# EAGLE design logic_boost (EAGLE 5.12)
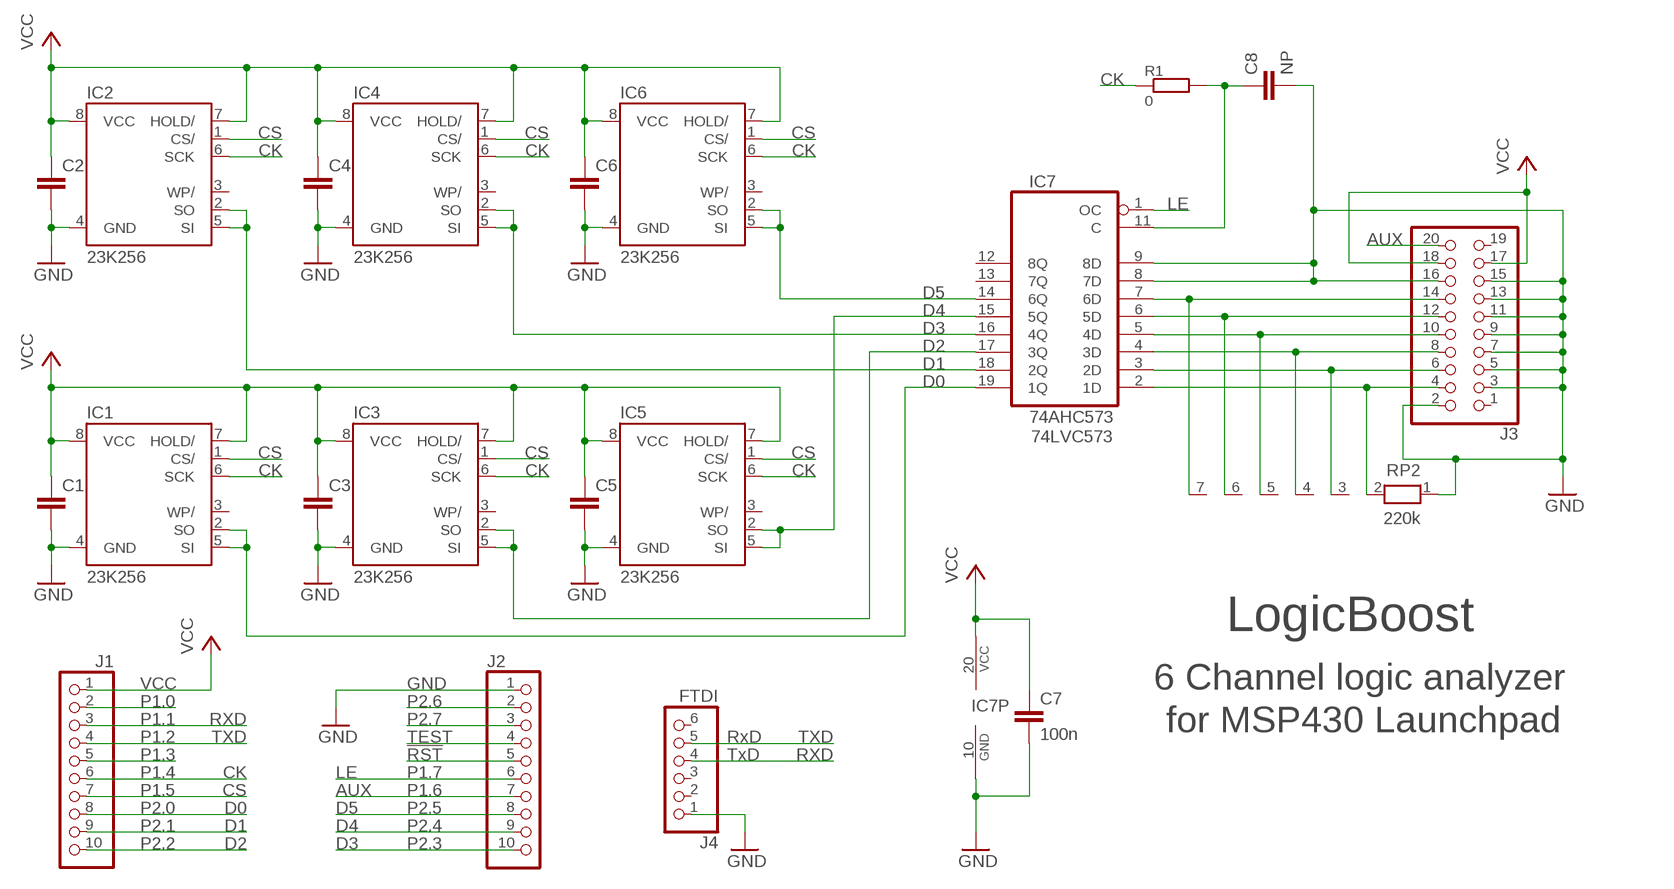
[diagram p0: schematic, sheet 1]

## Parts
C1  C-EU025-025X050  [C025-025X050]
C2  C-EU025-025X050  [C025-025X050]
C3  C-EU025-025X050  [C025-025X050]
C4  C-EU025-025X050  [C025-025X050]
C5  C-EU025-025X050  [C025-025X050]
C6  C-EU025-025X050  [C025-025X050]
C7  100n  C-EU025-025X050  [C025-025X050]
C8  NP  C-EU025-025X050  [C025-025X050]
IC1  23K256  AT25P  [DIL08]
IC2  23K256  AT25P  [DIL08]
IC3  23K256  AT25P  [DIL08]
IC4  23K256  AT25P  [DIL08]
IC5  23K256  AT25P  [DIL08]
IC6  23K256  AT25P  [DIL08]
IC7  74AHC573  74HC573N  [DIL20]
J1  PH1X10OCT076  [PH1X10OCT76]
J2  PH1X10OCT076  [PH1X10OCT76]
J3  PINHD-2X10  [2X10]
J4  FTDI  PH1X6OCT76  [PH1X6OCT76]
R1  0  EW30  [EW30]
RP2  220k  RN06  [RN-7]

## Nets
!RST: J2.5
AUX: J2.7 J3.20
CK: IC1.6(SCK) IC2.6(SCK) IC3.6(SCK) IC4.6(SCK) IC5.6(SCK) IC6.6(SCK) J1.6 R1.1
CS: IC1.1(CS/) IC2.1(CS/) IC3.1(CS/) IC4.1(CS/) IC5.1(CS/) IC6.1(CS/) J1.7
D0: IC1.2(SO) IC1.5(SI) IC7.19(1Q) J1.8
D1: IC2.2(SO) IC2.5(SI) IC7.18(2Q) J1.9
D2: IC3.2(SO) IC3.5(SI) IC7.17(3Q) J1.10
D3: IC4.2(SO) IC4.5(SI) IC7.16(4Q) J2.10
D4: IC5.2(SO) IC5.5(SI) IC7.15(5Q) J2.9
D5: IC6.2(SO) IC6.5(SI) IC7.14(6Q) J2.8
GND: C1.2 C2.2 C3.2 C4.2 C5.2 C6.2 C7.2 C8.2 IC1.4(GND) IC2.4(GND) IC3.4(GND) IC4.4(GND) IC5.4(GND) IC6.4(GND) IC7.8(7D) IC7.9(8D) IC7.10(GND) J2.1 J3.2 J3.3 J3.5 J3.7 J3.9 J3.11 J3.13 J3.15 J3.16 J4.1 RP2.1
LE: IC7.1(OC) J2.6
N$2: C8.1 IC7.11(C) R1.2
N$3: IC7.2(1D) J3.4 RP2.2
N$4: IC7.3(2D) J3.6 RP2.3
N$5: IC7.4(3D) J3.8 RP2.4
N$6: IC7.5(4D) J3.10 RP2.5
N$7: IC7.6(5D) J3.12 RP2.6
N$8: IC7.7(6D) J3.14 RP2.7
P1.0: J1.2
P1.3: J1.5
P2.6: J2.2
P2.7: J2.3
RXD: J1.3 J4.4
TEST: J2.4
TXD: J1.4 J4.5
VCC: C1.1 C2.1 C3.1 C4.1 C5.1 C6.1 C7.1 IC1.7(HOLD/) IC1.8(VCC) IC2.7(HOLD/) IC2.8(VCC) IC3.7(HOLD/) IC3.8(VCC) IC4.7(HOLD/) IC4.8(VCC) IC5.7(HOLD/) IC5.8(VCC) IC6.7(HOLD/) IC6.8(VCC) IC7.20(VCC) J1.1 J3.17 J3.18
Unconnected: IC1.3(WP/) IC2.3(WP/) IC3.3(WP/) IC4.3(WP/) IC5.3(WP/) IC6.3(WP/) IC7.12(8Q) IC7.13(7Q) J3.1 J3.19 J4.2 J4.3 J4.6

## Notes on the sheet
- 74LVC573
- LogicBoost
- 6 Channel logic analyzer
- P1.1
- for MSP430 Launchpad
- P1.2 | RxD
- TxD
- P1.4 | P1.7
- P1.5 | P1.6
- P2.0 | P2.5
- P2.1 | P2.4
- P2.2 | P2.3

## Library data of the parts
C1-C8 = rcl:C-EU: CAPACITOR, European symbol
IC1-IC6 = atmel:AT25*: SPI bus serial EEPROM; MPN: CAT25040LI-G; OC_FARNELL: 1718045; OC_NEWARK: 06R0588
IC7 = 74xx-us:74*573: 8-bit D latch BUS DRIVER
J1 J2 = MY_CONN:PH1X10
J3 = pinhead:PINHD-2X10: PIN HEADER
J4 = MY_CONN:PH1X6
R1 = my_resistor:EW30
RP2 = resistor-net:RN06: RESISTOR NETWORK; OC_FARNELL: unknown; OC_NEWARK: unknown

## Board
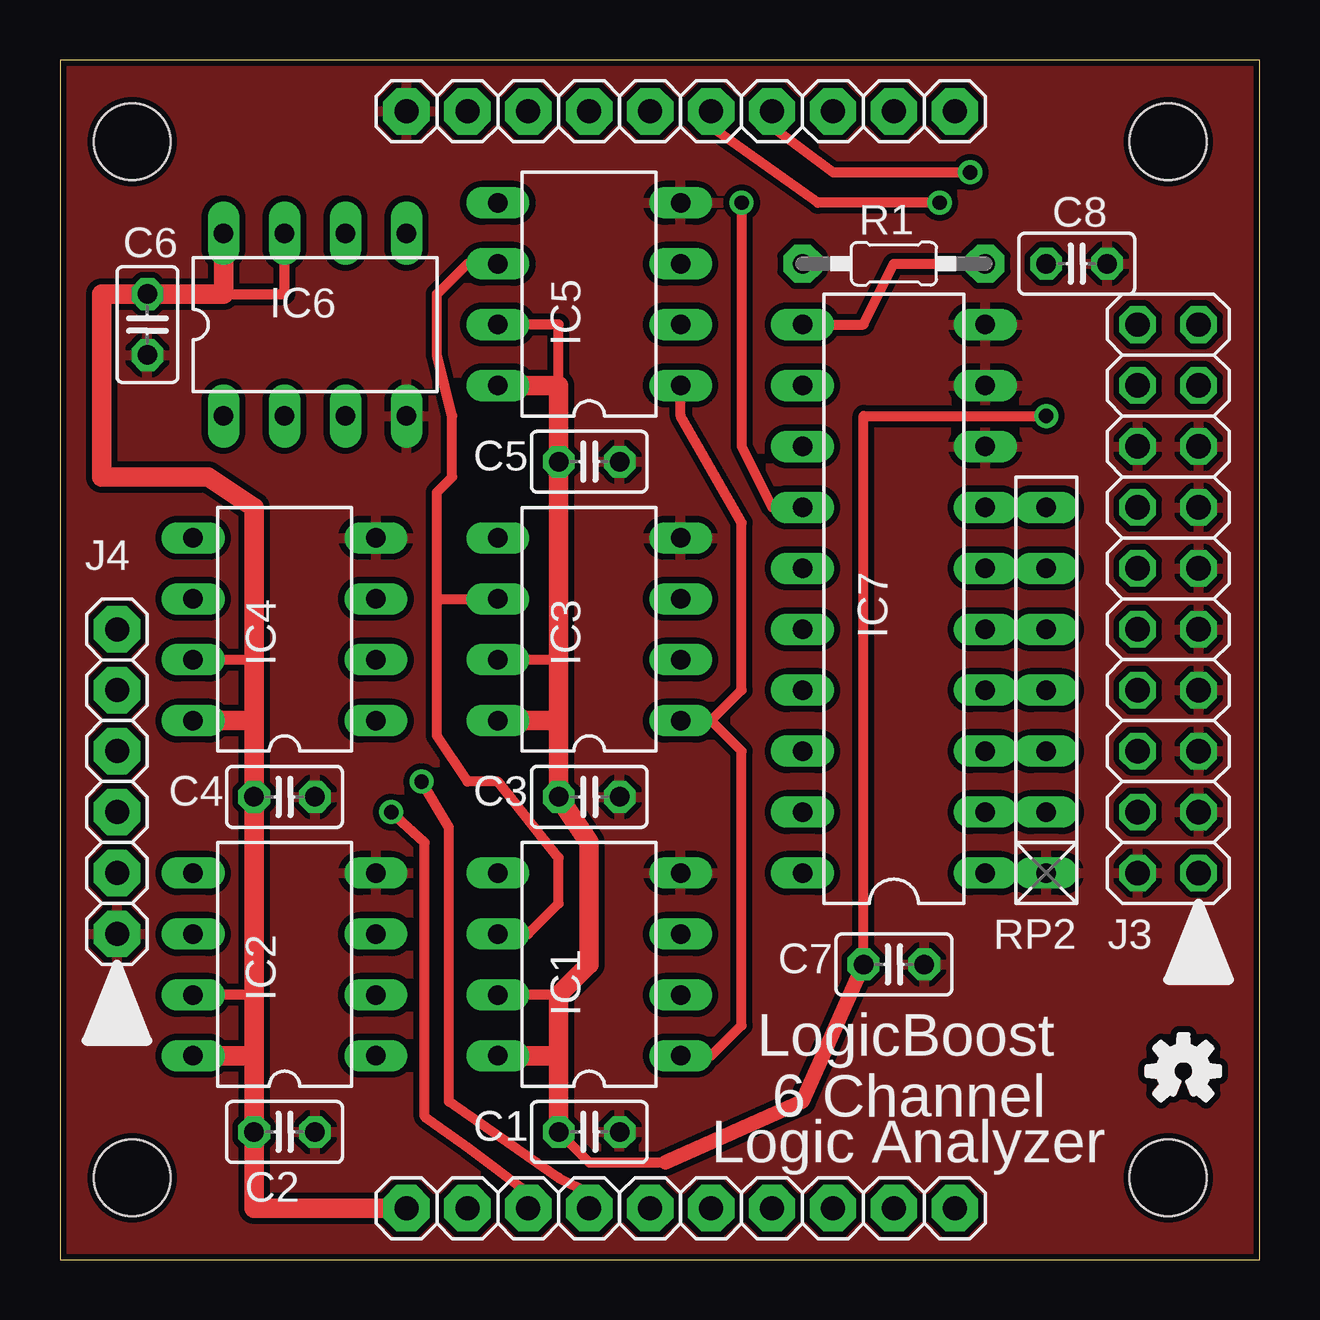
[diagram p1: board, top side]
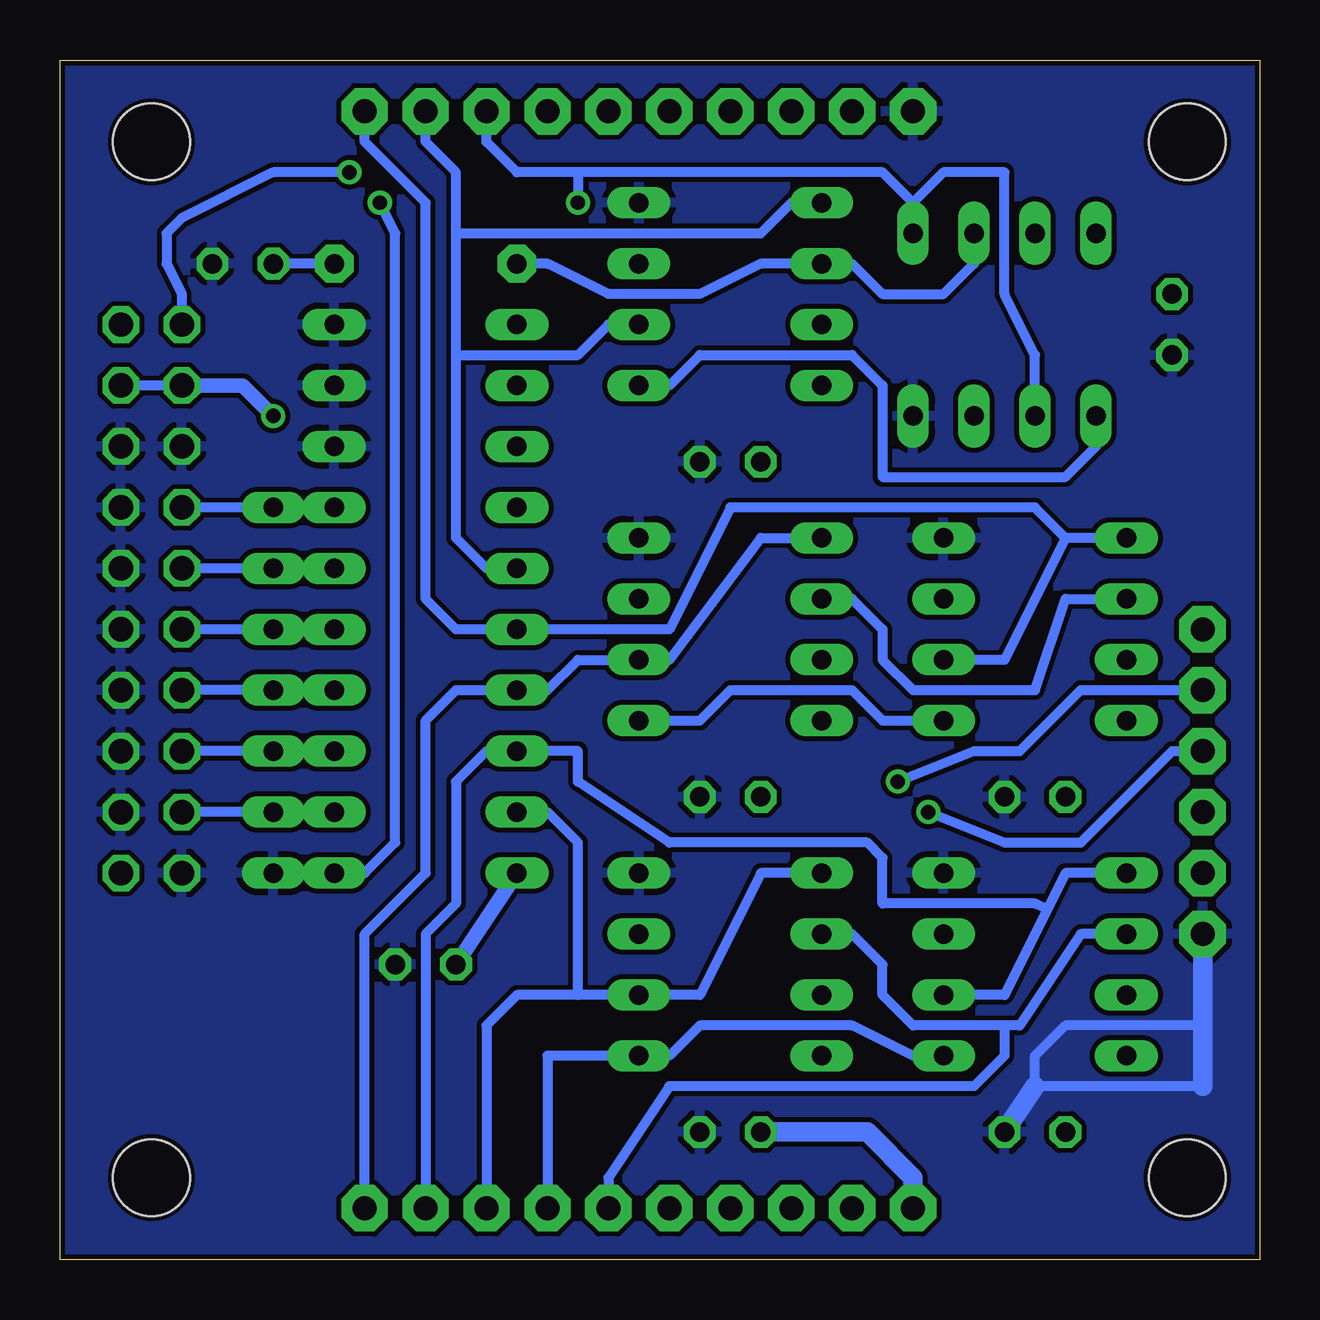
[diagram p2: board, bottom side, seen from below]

Size 50 x 50 mm. Coordinates in mm from the lower left corner, seen from the top.
Outline: 0,0 50,0 50,50 0,50 0,0
Copper layers (1*16): Top 0.035mm / dielectric 1.5mm / Bottom 0.035mm
Design rules "default *": minimum track width 10mil, minimum drill 24mil, track to track 8mil, track to pad 8mil, pad to pad 8mil, via to via 8mil, smd to smd 8mil, copper to edge 8mil, drill to drill 8mil, minimum pad ring 10mil, minimum via ring 8mil, stop-mask expansion 4mil, vias tented up to drill 0mil, thermal gap 10mil
Holes 3.2 mm at 46.19,46.59 46.19,3.41 3.01,3.41 3.01,46.59

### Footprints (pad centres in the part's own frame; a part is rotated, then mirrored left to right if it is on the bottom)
C025-025X050 = drill 0.813 octagon: 1 -1.27,0; 2 1.27,0
DIL08 = drill 0.813 long: 1 -3.81,-3.81; 2 -1.27,-3.81; 3 1.27,-3.81; 4 3.81,-3.81; 5 3.81,3.81; 6 1.27,3.81; 7 -1.27,3.81; 8 -3.81,3.81
DIL20 = drill 0.813 long: 1 -11.43,-3.81; 2 -8.89,-3.81; 3 -6.35,-3.81; 4 -3.81,-3.81; 5 -1.27,-3.81; 6 1.27,-3.81; 7 3.81,-3.81; 8 6.35,-3.81; 9 8.89,-3.81; 10 11.43,-3.81; 11 11.43,3.81; 12 8.89,3.81; 13 6.35,3.81; 14 3.81,3.81; 15 1.27,3.81; 16 -1.27,3.81; 17 -3.81,3.81; 18 -6.35,3.81; 19 -8.89,3.81; 20 -11.43,3.81
PH1X10OCT76 = drill 1 pad 1.93 octagon: 1 0,0; 2 2.54,0; 3 5.08,0; 4 7.62,0; 5 10.16,0; 6 12.7,0; 7 15.24,0; 8 17.78,0; 9 20.32,0; 10 22.86,0
2X10 = drill 1.016 octagon: 1 -11.43,-1.27; 2 -11.43,1.27; 3 -8.89,-1.27; 4 -8.89,1.27; 5 -6.35,-1.27; 6 -6.35,1.27; 7 -3.81,-1.27; 8 -3.81,1.27; 9 -1.27,-1.27; 10 -1.27,1.27; 11 1.27,-1.27; 12 1.27,1.27; 13 3.81,-1.27; 14 3.81,1.27; 15 6.35,-1.27; 16 6.35,1.27; 17 8.89,-1.27; 18 8.89,1.27; 19 11.43,-1.27; 20 11.43,1.27
PH1X6OCT76 = drill 1 pad 1.93 octagon: 1 0,0; 2 2.54,0; 3 5.08,0; 4 7.62,0; 5 10.16,0; 6 12.7,0
EW30 = drill 0.813 pad 1.6 octagon: 1 -5.08,0; 2 2.54,0
RN-7 = drill 0.813 long: 1 -7.62,0; 2 -5.08,0; 3 -2.54,0; 4 0,0; 5 2.54,0; 6 5.08,0; 7 7.62,0

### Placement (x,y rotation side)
C1  22.06,5.31 0 top
C2  9.36,5.31 0 top
C3  22.06,19.29 0 top
C4  9.36,19.29 0 top
C5  22.06,33.26 0 top
C6  3.65,38.97 270 top
C7  34.76,12.3 0 top
C8  42.38,41.51 0 top
IC1  22.06,12.3 90 top
IC2  9.36,12.3 90 top
IC3  22.06,26.27 90 top
IC4  9.36,26.27 90 top
IC5  22.06,40.24 90 top
IC6  10.63,38.97 0 top
IC7  34.76,27.54 90 top
J1  14.44,2.14 0 top
J2  14.44,47.86 0 top
J3  46.19,27.54 90 top
J4  2.38,13.57 90 top
R1  36.03,41.51 0 top
RP2  41.11,23.73 90 top

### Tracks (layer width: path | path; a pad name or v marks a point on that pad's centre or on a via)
AUX  (via drill 0.6)
  Top 0.406: J2.7 29.68,47.23 32.22,45.32 v37.94,45.32
  Bottom 0.406: J3.20 44.92,40.24 45.55,41.51 45.55,42.78 44.92,43.41 41.11,45.32 v37.94,45.32
CK
  Top 0.406: 15.71,27.54 IC3.6 | IC5.6 16.98,41.51 15.71,40.24 15.71,37.7 16.34,35.16 16.34,32.62 15.71,31.98 15.71,27.54 | IC1.6 19.52,13.57 20.79,14.84 20.79,16.75 18.25,19.92 16.98,19.92 15.71,21.83 15.71,27.54
  Bottom 0.406: 10.63,9.76 9.99,9.76 7.46,13.57 IC2.6 | 10.63,9.76 14.44,9.76 15.71,11.03 15.71,12.3 16.98,13.57 IC1.6 | 10.63,9.76 10.63,8.49 11.9,7.22 24.6,7.22 27.14,3.41 J1.6 | IC6.6 11.9,41.51 13.17,40.24 15.71,40.24 16.98,41.51 IC5.6 20.79,41.51 23.33,40.24 27.14,40.24 29.68,41.51 R1.1 | IC4.6 8.09,27.54 9.36,23.73 14.44,23.73 15.71,25 15.71,26.27 16.98,27.54 IC3.6
CS
  Top 0.406: 27.14,22.46 IC3.1 | 27.14,22.46 28.41,23.73 28.41,30.71 25.87,35.16 IC5.1 | IC1.1 27.14,8.49 28.41,9.76 28.41,21.19 27.14,22.46
  Bottom 0.406: J1.7 29.68,8.49 IC1.1 24.6,8.49 23.33,9.76 16.98,9.76 14.44,8.49 IC2.1 | IC5.1 24.6,36.43 23.33,37.7 16.98,37.7 15.71,36.43 15.71,32.62 8.09,32.62 6.82,33.89 IC6.1 | IC3.1 23.33,22.46 22.06,23.73 16.98,23.73 15.71,22.46 IC4.1
D0
  Bottom 0.406: IC7.19 29.68,18.65 28.41,17.38 28.41,11.03 | J1.8 32.22,9.76 30.95,11.03 28.41,11.03 | 28.41,11.03 IC1.2 23.33,11.03 20.79,16.11 IC1.5
D1
  Bottom 0.406: IC2.5 8.09,16.11 8.85,14.59 | IC2.2 10.63,11.03 8.85,14.59 | J1.9 34.76,13.57 33.49,14.84 33.49,19.92 32.22,21.19 IC7.18 28.41,21.19 28.41,19.92 24.6,17.38 16.34,17.38 15.71,16.75 15.71,14.84 9.36,14.84 8.85,14.59
D2
  Bottom 0.406: IC3.5 20.79,30.08 24.6,25 IC3.2 28.41,25 29.68,23.73 IC7.17 33.49,23.73 34.76,22.46 34.76,16.11 37.3,13.57 J1.10
D3
  Bottom 0.406: IC4.2 10.63,25 8.09,30.08 | IC4.5 8.09,30.08 | 8.09,30.08 9.36,31.35 22.06,31.35 24.6,26.27 IC7.16 33.49,26.27 34.76,27.54 34.76,44.05 37.3,46.59 J2.10
D4
  Bottom 0.406: IC7.15 32.22,28.81 33.49,30.08 33.49,37.7 | 33.49,37.7 33.49,42.78 | 33.49,42.78 33.49,45.32 34.76,46.59 J2.9 | IC5.2 27.14,38.97 28.41,37.7 33.49,37.7 | IC5.5 19.52,44.05 20.79,42.78 33.49,42.78
D5  (via drill 0.6)
  Top 0.406: IC7.14 29.68,31.35 28.41,33.89 v28.41,44.05
  Bottom 0.406: IC6.2 9.36,37.7 10.63,40.24 10.63,45.32 13.17,45.32 14.44,44.05 | 28.41,45.32 15.71,45.32 14.44,44.05 | 14.44,44.05 IC6.5 | 28.41,45.32 v28.41,44.05 | 28.41,45.32 30.95,45.32 32.22,46.59 J2.8
GND
  Bottom 0.406: 2.38,7.22 9.36,7.22 9.36,8.49 8.09,9.76 2.38,9.76
  Bottom 0.813: 2.38,7.22 2.38,9.76 J4.1 | 9.36,7.22 C2.2
  pour Top (isolate 0.254): -0.17,49.77 50,49.77 50,0.23 -0.17,0.23
  pour Bottom: -0.8,50.4 -0.8,-0.4 50,-0.4 50,50.4
LE  (via drill 0.6)
  Top 0.406: v36.67,44.05 31.58,44.05 27.14,47.23 J2.6
  Bottom 0.406: v36.67,44.05 36.03,42.78 36.03,17.38 37.3,16.11 IC7.1
N$1
  Top 0.203: 47.23,6.89 arc9 47.38,6.97 47.76,6.65 48.03,6.92 47.71,7.3 arc19 47.85,7.62 48.34,7.67 48.34,8.04 47.85,8.09 arc19 47.71,8.41 48.03,8.79 47.76,9.06 47.38,8.74 arc19 47.06,8.88 47.01,9.37 46.64,9.37 46.59,8.88 arc19 46.27,8.74 45.89,9.06 45.62,8.79 45.94,8.41 arc19 45.8,8.09 45.31,8.04 45.31,7.67 45.8,7.62 arc19 45.94,7.3 45.62,6.92 45.89,6.65 46.27,6.97 arc9 46.42,6.89 46.64,7.42 arc-68 46.35,7.86 arc-247 47.01,7.42 47.23,6.89
N$2
  Top 0.406: R1.2 34.76,41.51 33.49,38.97 IC7.11
  Bottom 0.406: R1.2 C8.1
N$3
  Bottom 0.406: IC7.2 RP2.2 J3.4
N$4
  Bottom 0.406: J3.6 RP2.3 IC7.3
N$5
  Bottom 0.406: IC7.4 RP2.4 J3.8
N$6
  Bottom 0.406: IC7.5 RP2.5 J3.10
N$7
  Bottom 0.406: IC7.6 RP2.6 J3.12
N$8
  Bottom 0.406: IC7.7 RP2.7 J3.14
RXD  (via drill 0.6)
  Top 0.406: v13.8,18.65 15.2,17.38 15.2,5.95 16.98,4.68 19.52,2.77 J1.3
  Bottom 0.406: J4.4 3.65,21.19 7.46,17.38 10.63,17.38 v13.8,18.65
TXD  (via drill 0.6)
  Top 0.406: J1.4 22.06,2.77 20.79,3.41 16.22,6.58 16.22,18.02 v15.07,19.92
  Bottom 0.406: J4.5 7.46,23.73 9.99,21.19 11.9,21.19 v15.07,19.92
VCC  (via drill 0.6)
  Top 0.406: 8.09,25 IC4.7 | IC5.7 20.79,38.97 20.79,36.43 | 20.79,25 IC3.7 | 8.09,11.03 IC2.7 | 20.79,11.03 IC1.7 | IC6.7 9.36,40.24 6.82,40.24 | 25.23,4.04 22.06,4.04 C1.1 | v41.11,35.16 33.49,35.16 C7.1
  Top 0.61: C7.1 30.95,6.58 25.23,4.04
  Top 0.813: 8.09,8.49 C2.1 8.09,2.14 J1.1 | 8.09,8.49 8.09,11.03 C4.1 8.09,22.46 | 8.09,22.46 8.09,25 8.09,31.35 6.19,32.62 1.74,32.62 1.74,40.24 C6.1 6.82,40.24 IC6.8 | 8.09,22.46 IC4.8 | 8.09,8.49 IC2.8 | IC5.8 20.79,36.43 C5.1 20.79,25 20.79,22.46 | 20.79,8.49 20.79,11.03 22.06,12.3 22.06,17.38 C3.1 20.79,22.46 | 20.79,8.49 IC1.8 | 20.79,22.46 IC3.8 | C1.1 20.79,8.49
  Bottom 0.406: J3.18 J3.17
  Bottom 0.61: C7.1 IC7.20 | J3.18 42.38,36.43 v41.11,35.16
  Bottom 0.813: C1.1 16.34,5.31 14.44,3.41 J1.1

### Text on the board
tPlace: 6 Channel | Logic Analyzer
tNames: LogicBoost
